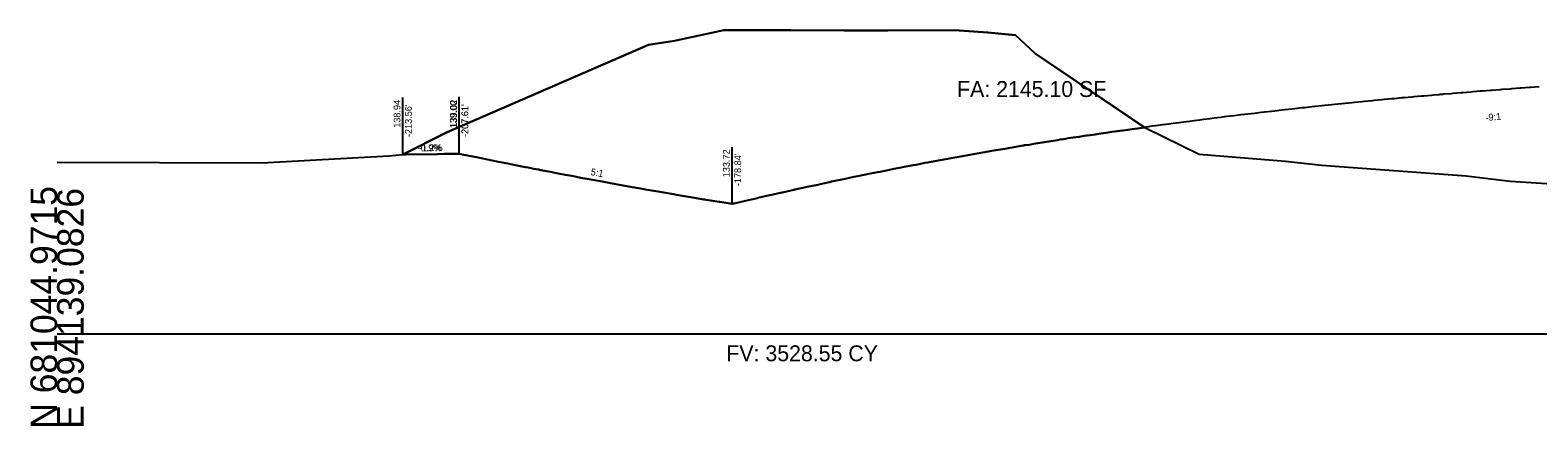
# Model space of a CAD drawing. Extents: x -26 to 4403, y -13 to 9578.
# Drawn here: x 1997.2 to 2156.1, y 490.3 to 532.1 of the extents above; entities that cross this region are included whole.
import ezdxf

# ---------------------------------------------------------------- set-up
doc = ezdxf.new("R2010")
doc.units = 0
for name, color, linetype in [('Draft_XS_Grid', 7, 'Continuous'), ('DRAINAGE_SPUR_DIKES', 7, 'Continuous'), ('DTM_CORRIDOR', 7, 'Continuous'), ('DTM_X_GROUND', 7, 'Continuous'), ('SLOPE_STAKES_FILL', 7, 'Continuous'), ('XS_CELL', 7, 'Continuous'), ('XS_M_SHAPES_EARTHWORK', 7, 'Continuous'), ('XS_P_GROUND', 7, 'Continuous'), ('XS_P_TX_CLEARZONE', 7, 'Continuous'), ('XS_P_TX_FS_BS', 7, 'Continuous'), ('XS_SHEET_EW_TX_AREA', 7, 'Continuous'), ('XS_SHEET_EW_TX_VOLUME', 7, 'Continuous')]:
    doc.layers.add(name, color=color, linetype=linetype)

msp = doc.modelspace()

# ---------------------------------------------------------------- linework, layer by layer
at = {"layer": 'DTM_X_GROUND'}
msp.add_lwpolyline([(2000, 518.14), (2021.58, 518.06), (2034.99, 518.8), (2035.72, 518.86), (2036.44, 518.94), (2041.12, 521.3), (2062.37, 530.51), (2065.11, 530.92), (2070.29, 532.04), (2077.35, 532.04), (2082.97, 532.02), (2087.59, 532.02), (2094.63, 532.05), (2098.14, 531.79), (2101.06, 531.53), (2103.12, 529.59), (2114.67, 521.78), (2120.42, 518.96), (2129.5, 518.23), (2133.32, 517.8), (2148.57, 516.67), (2153.19, 516.13), (2186.74, 513.99)], dxfattribs=at)
at = {"layer": 'XS_CELL'}
msp.add_line((2000, 500), (2250, 500), dxfattribs=at)
at = {"layer": 'XS_M_SHAPES_EARTHWORK'}
msp.add_lwpolyline([(2036.44, 518.94), (2041.12, 521.3), (2062.37, 530.51), (2065.11, 530.92), (2070.29, 532.04), (2077.35, 532.04), (2082.97, 532.02), (2087.59, 532.02), (2094.63, 532.05), (2098.14, 531.79), (2101.06, 531.53), (2103.12, 529.59), (2114.66, 521.79), (2114.43, 521.76), (2113.93, 521.69), (2113.34, 521.61), (2112.9, 521.55), (2112.37, 521.48), (2112.32, 521.47), (2112.33, 521.47), (2111.76, 521.39), (2111.2, 521.31), (2110.61, 521.23), (2110.06, 521.15), (2109.46, 521.06), (2108.91, 520.98), (2108.3, 520.89), (2107.77, 520.81), (2107.14, 520.72), (2106.62, 520.64), (2106.33, 520.59), (2106.1, 520.55), (2105.75, 520.5), (2105.47, 520.46), (2104.82, 520.35), (2104.32, 520.27), (2103.65, 520.17), (2103.17, 520.09), (2102.49, 519.97), (2102.01, 519.9), (2101.92, 519.88), (2101.86, 519.87), (2101.25, 519.77), (2100.86, 519.7), (2100.14, 519.58), (2099.7, 519.51), (2098.97, 519.38), (2098.54, 519.31), (2097.8, 519.18), (2097.39, 519.11), (2096.63, 518.97), (2096.23, 518.9), (2095.45, 518.76), (2095.07, 518.69), (2094.28, 518.55), (2093.91, 518.48), (2093.49, 518.41), (2093.31, 518.37), (2092.89, 518.3), (2092.72, 518.27), (2091.82, 518.1), (2091.49, 518.04), (2090.57, 517.86), (2090.25, 517.8), (2089.31, 517.62), (2089.01, 517.56), (2088.05, 517.37), (2087.76, 517.32), (2086.78, 517.12), (2086.51, 517.07), (2086.19, 517), (2086.11, 516.99), (2085.42, 516.85), (2085.26, 516.82), (2084.23, 516.6), (2084, 516.56), (2082.95, 516.34), (2082.74, 516.29), (2081.66, 516.07), (2081.48, 516.03), (2081.28, 515.98), (2081.24, 515.98), (2080.34, 515.78), (2080.21, 515.75), (2079.08, 515.51), (2078.94, 515.48), (2077.79, 515.23), (2077.67, 515.2), (2076.49, 514.94), (2076.4, 514.92), (2075.19, 514.65), (2075.12, 514.63), (2073.89, 514.35), (2073.84, 514.34), (2072.59, 514.06), (2072.57, 514.05), (2071.38, 513.77), (2071.37, 513.77), (2071.28, 513.75), (2071.16, 513.72), (2069.86, 513.93), (2069.8, 513.94), (2068.44, 514.16), (2068.31, 514.18), (2068.17, 514.2), (2066.81, 514.43), (2066.58, 514.47), (2065.29, 514.69), (2064.98, 514.74), (2063.75, 514.95), (2063.36, 515.02), (2062.21, 515.22), (2062.04, 515.25), (2061.67, 515.31), (2061.33, 515.37), (2060.64, 515.49), (2060.06, 515.6), (2059.07, 515.78), (2058.17, 515.94), (2057.48, 516.07), (2056.65, 516.22), (2055.88, 516.37), (2055.41, 516.45), (2054.91, 516.55), (2054.61, 516.6), (2054.27, 516.67), (2053.57, 516.8), (2052.64, 516.98), (2052.01, 517.1), (2051.01, 517.29), (2050.75, 517.34), (2050.28, 517.43), (2049.66, 517.56), (2049.36, 517.61), (2048.14, 517.86), (2047.71, 517.94), (2046.35, 518.21), (2046.05, 518.27), (2044.55, 518.58), (2044.38, 518.61), (2042.72, 518.95), (2042.7, 518.95), (2042.39, 519), (2042.38, 519), (2042.27, 519), (2042.06, 519), (2041.95, 519), (2041.72, 518.99), (2041.65, 518.99), (2041.46, 518.99), (2041.43, 518.99), (2041.34, 518.99), (2041.33, 518.99), (2040.84, 518.99), (2040.09, 518.98), (2036.77, 518.95)], close=True, dxfattribs=at)
msp.add_lwpolyline([(2156.26, 526.07), (2155.38, 526), (2155.23, 525.99), (2154.35, 525.93), (2154.21, 525.92), (2153.33, 525.85), (2153.18, 525.84), (2152.31, 525.78), (2152.15, 525.76), (2151.28, 525.7), (2151.12, 525.68), (2150.26, 525.62), (2150.08, 525.6), (2149.23, 525.53), (2149.05, 525.52), (2148.2, 525.45), (2148.02, 525.44), (2147.17, 525.37), (2146.98, 525.35), (2146.14, 525.28), (2146.09, 525.27), (2145.84, 525.25), (2145.71, 525.24), (2145.13, 525.19), (2144.92, 525.17), (2144.09, 525.1), (2143.87, 525.08), (2143.06, 525.01), (2142.83, 524.99), (2142.02, 524.92), (2141.78, 524.9), (2140.98, 524.82), (2140.74, 524.8), (2139.94, 524.73), (2139.69, 524.7), (2138.89, 524.63), (2138.64, 524.6), (2137.85, 524.53), (2137.58, 524.5), (2136.8, 524.42), (2136.53, 524.39), (2135.76, 524.32), (2135.47, 524.29), (2134.71, 524.21), (2134.42, 524.18), (2133.66, 524.1), (2133.36, 524.07), (2132.6, 523.99), (2132.3, 523.96), (2131.55, 523.87), (2131.23, 523.84), (2130.5, 523.76), (2130.17, 523.72), (2129.44, 523.64), (2129.1, 523.6), (2128.38, 523.52), (2128.03, 523.48), (2127.32, 523.4), (2126.96, 523.36), (2126.25, 523.27), (2125.89, 523.23), (2125.19, 523.15), (2124.81, 523.1), (2124.12, 523.02), (2123.73, 522.97), (2123.05, 522.89), (2122.65, 522.84), (2121.98, 522.76), (2121.57, 522.7), (2120.91, 522.62), (2120.49, 522.57), (2119.84, 522.48), (2119.4, 522.43), (2118.76, 522.34), (2118.31, 522.28), (2117.68, 522.2), (2117.22, 522.14), (2116.6, 522.06), (2116.13, 521.99), (2115.51, 521.91), (2115.03, 521.85), (2114.66, 521.79), (2114.67, 521.78), (2120.42, 518.96), (2129.5, 518.23), (2133.32, 517.8), (2148.57, 516.67), (2153.19, 516.13), (2186.74, 513.99)], dxfattribs=at)
at = {"layer": 'XS_P_GROUND'}
for points in [[(2114.66, 521.79), (2103.12, 529.59), (2101.06, 531.53), (2098.14, 531.79), (2094.63, 532.05), (2087.59, 532.02), (2082.97, 532.02), (2077.35, 532.04), (2070.29, 532.04), (2065.11, 530.92), (2062.37, 530.51), (2041.12, 521.3), (2036.44, 518.94)], [(2156.26, 526.07), (2155.38, 526), (2155.23, 525.99), (2154.35, 525.93), (2154.21, 525.92), (2153.33, 525.85), (2153.18, 525.84), (2152.31, 525.78), (2152.15, 525.76), (2151.28, 525.7), (2151.12, 525.68), (2150.26, 525.62), (2150.08, 525.6), (2149.23, 525.53), (2149.05, 525.52), (2148.2, 525.45), (2148.02, 525.44), (2147.17, 525.37), (2146.98, 525.35), (2146.14, 525.28), (2146.09, 525.27), (2145.84, 525.25), (2145.71, 525.24), (2145.13, 525.19), (2144.92, 525.17), (2144.09, 525.1), (2143.87, 525.08), (2143.06, 525.01), (2142.83, 524.99), (2142.02, 524.92), (2141.78, 524.9), (2140.98, 524.82), (2140.74, 524.8), (2139.94, 524.73), (2139.69, 524.7), (2138.89, 524.63), (2138.64, 524.6), (2137.85, 524.53), (2137.58, 524.5), (2136.8, 524.42), (2136.53, 524.39), (2135.76, 524.32), (2135.47, 524.29), (2134.71, 524.21), (2134.42, 524.18), (2133.66, 524.1), (2133.36, 524.07), (2132.6, 523.99), (2132.3, 523.96), (2131.55, 523.87), (2131.23, 523.84), (2130.5, 523.76), (2130.17, 523.72), (2129.44, 523.64), (2129.1, 523.6), (2128.38, 523.52), (2128.03, 523.48), (2127.32, 523.4), (2126.96, 523.36), (2126.25, 523.27), (2125.89, 523.23), (2125.19, 523.15), (2124.81, 523.1), (2124.12, 523.02), (2123.73, 522.97), (2123.05, 522.89), (2122.65, 522.84), (2121.98, 522.76), (2121.57, 522.7), (2120.91, 522.62), (2120.49, 522.57), (2119.84, 522.48), (2119.4, 522.43), (2118.76, 522.34), (2118.31, 522.28), (2117.68, 522.2), (2117.22, 522.14), (2116.6, 522.06), (2116.13, 521.99), (2115.51, 521.91), (2115.03, 521.85), (2114.43, 521.76), (2113.93, 521.69), (2113.34, 521.61), (2112.9, 521.55), (2112.37, 521.48), (2112.32, 521.47), (2112.33, 521.47), (2111.76, 521.39), (2111.2, 521.31), (2110.61, 521.23), (2110.06, 521.15), (2109.46, 521.06), (2108.91, 520.98), (2108.3, 520.89), (2107.77, 520.81), (2107.14, 520.72), (2106.62, 520.64), (2106.33, 520.59), (2106.1, 520.55), (2105.75, 520.5), (2105.47, 520.46), (2104.82, 520.35), (2104.32, 520.27), (2103.65, 520.17), (2103.17, 520.09), (2102.49, 519.97), (2102.01, 519.9), (2101.92, 519.88), (2101.86, 519.87), (2101.25, 519.77), (2100.86, 519.7), (2100.14, 519.58), (2099.7, 519.51), (2098.97, 519.38), (2098.54, 519.31), (2097.8, 519.18), (2097.39, 519.11), (2096.63, 518.97), (2096.23, 518.9), (2095.45, 518.76), (2095.07, 518.69), (2094.28, 518.55), (2093.91, 518.48), (2093.49, 518.41), (2093.31, 518.37), (2092.89, 518.3), (2092.72, 518.27), (2091.82, 518.1), (2091.49, 518.04), (2090.57, 517.86), (2090.25, 517.8), (2089.31, 517.62), (2089.01, 517.56), (2088.05, 517.37), (2087.76, 517.32), (2086.78, 517.12), (2086.51, 517.07), (2086.19, 517), (2086.11, 516.99), (2085.42, 516.85), (2085.26, 516.82), (2084.23, 516.6), (2084, 516.56), (2082.95, 516.34), (2082.74, 516.29), (2081.66, 516.07), (2081.48, 516.03), (2081.28, 515.98), (2081.24, 515.98), (2080.34, 515.78), (2080.21, 515.75), (2079.08, 515.51), (2078.94, 515.48), (2077.79, 515.23), (2077.67, 515.2), (2076.49, 514.94), (2076.4, 514.92), (2075.19, 514.65), (2075.12, 514.63), (2073.89, 514.35), (2073.84, 514.34), (2072.59, 514.06), (2072.57, 514.05), (2071.38, 513.77), (2071.37, 513.77), (2071.28, 513.75), (2071.28, 513.75), (2071.16, 513.72)], [(2086.19, 517), (2086.51, 517.07), (2086.78, 517.12), (2087.76, 517.32), (2088.05, 517.37), (2089.01, 517.56), (2089.31, 517.62), (2090.25, 517.8), (2090.57, 517.86), (2091.49, 518.04), (2091.82, 518.1), (2092.72, 518.27), (2092.89, 518.3), (2093.31, 518.37), (2093.49, 518.41), (2093.91, 518.48), (2094.28, 518.55), (2095.07, 518.69), (2095.45, 518.76), (2096.23, 518.9), (2096.63, 518.97), (2097.39, 519.11), (2097.8, 519.18), (2098.54, 519.31), (2098.97, 519.38), (2099.7, 519.51), (2100.14, 519.58), (2100.86, 519.7), (2101.25, 519.77), (2101.86, 519.87), (2101.92, 519.88), (2102.01, 519.9), (2102.49, 519.97), (2103.17, 520.09), (2103.65, 520.17), (2104.32, 520.27), (2104.82, 520.35), (2105.47, 520.46), (2105.75, 520.5), (2106.1, 520.55), (2106.33, 520.59), (2106.62, 520.64), (2107.14, 520.72), (2107.77, 520.81), (2108.3, 520.89), (2108.91, 520.98), (2109.46, 521.06), (2110.06, 521.15), (2110.61, 521.23), (2111.2, 521.31), (2111.76, 521.39), (2112.32, 521.47), (2112.33, 521.47)], [(2112.33, 521.47), (2112.37, 521.48), (2112.9, 521.55), (2113.34, 521.61), (2113.93, 521.69), (2114.43, 521.76), (2114.66, 521.79)], [(2112.33, 521.47), (2112.33, 521.47)], [(2042.06, 519), (2041.95, 519), (2041.72, 518.99), (2041.65, 518.99), (2041.46, 518.99), (2041.43, 518.99), (2041.34, 518.99), (2041.33, 518.99), (2040.84, 518.99), (2040.09, 518.98), (2036.77, 518.95), (2036.44, 518.94)], [(2036.44, 518.94), (2036.77, 518.95), (2040.09, 518.98), (2040.84, 518.99), (2041.33, 518.99), (2041.34, 518.99), (2041.43, 518.99), (2041.46, 518.99), (2041.65, 518.99), (2041.72, 518.99), (2041.95, 519), (2042.06, 519)], [(2042.39, 519), (2042.38, 519), (2042.27, 519), (2042.06, 519)], [(2042.06, 519), (2042.27, 519), (2042.39, 519)], [(2042.39, 519), (2042.7, 518.95), (2042.72, 518.95), (2044.38, 518.61), (2044.55, 518.58), (2046.05, 518.27), (2046.35, 518.21), (2047.71, 517.94), (2048.14, 517.86), (2049.36, 517.61), (2049.66, 517.56), (2050.28, 517.43), (2050.75, 517.34), (2051.01, 517.29), (2052.01, 517.1), (2052.64, 516.98), (2053.57, 516.8), (2054.27, 516.67), (2054.61, 516.6), (2054.91, 516.55), (2055.41, 516.45), (2055.88, 516.37), (2056.65, 516.22), (2057.48, 516.07), (2058.17, 515.94), (2059.07, 515.78), (2060.06, 515.6), (2060.64, 515.49), (2061.33, 515.37), (2061.67, 515.31), (2062.04, 515.25), (2062.21, 515.22), (2063.36, 515.02), (2063.75, 514.95), (2064.98, 514.74), (2065.29, 514.69), (2066.58, 514.47), (2066.81, 514.43), (2068.17, 514.2), (2068.31, 514.18), (2068.44, 514.16), (2069.8, 513.94), (2069.86, 513.93), (2071.16, 513.72)], [(2042.39, 519), (2042.7, 518.95), (2042.72, 518.95), (2044.38, 518.61), (2044.55, 518.58), (2046.05, 518.27), (2046.35, 518.21), (2047.71, 517.94), (2048.14, 517.86), (2049.36, 517.61), (2049.66, 517.56), (2050.28, 517.43), (2050.75, 517.34), (2051.01, 517.29), (2052.01, 517.1), (2052.64, 516.98), (2053.57, 516.8), (2054.27, 516.67), (2054.61, 516.6), (2054.91, 516.55), (2055.41, 516.45), (2055.88, 516.37), (2056.65, 516.22), (2057.48, 516.07), (2058.17, 515.94), (2059.07, 515.78), (2060.06, 515.6), (2060.64, 515.49), (2061.33, 515.37), (2061.67, 515.31), (2062.04, 515.25), (2062.21, 515.22), (2063.36, 515.02), (2063.75, 514.95), (2064.98, 514.74), (2065.29, 514.69), (2066.58, 514.47), (2066.81, 514.43), (2068.17, 514.2), (2068.31, 514.18), (2068.44, 514.16), (2069.8, 513.94), (2069.86, 513.93), (2071.16, 513.72)], [(2071.16, 513.72), (2071.28, 513.75), (2071.38, 513.77), (2072.57, 514.05), (2072.59, 514.06), (2073.84, 514.34), (2073.89, 514.35), (2075.12, 514.63), (2075.19, 514.65), (2076.4, 514.92), (2076.49, 514.94), (2077.67, 515.2), (2077.79, 515.23), (2078.94, 515.48), (2079.08, 515.51), (2080.21, 515.75), (2080.34, 515.78), (2081.24, 515.98), (2081.28, 515.98), (2081.48, 516.03), (2081.66, 516.07), (2082.74, 516.29), (2082.95, 516.34), (2084, 516.56), (2084.23, 516.6), (2085.26, 516.82), (2085.42, 516.85), (2086.11, 516.99), (2086.19, 517)]]:
    msp.add_lwpolyline(points, dxfattribs=at)
at = {"layer": 'XS_P_TX_CLEARZONE'}
for p, q in [((2036.44, 518.94), (2036.44, 524.94)), ((2036.44, 518.94), (2036.44, 524.94)), ((2036.44, 518.94), (2036.44, 524.94)), ((2036.44, 518.94), (2036.44, 524.94)), ((2036.44, 518.94), (2036.44, 524.94)), ((2036.44, 518.94), (2036.44, 524.94)), ((2036.44, 518.94), (2036.44, 524.94)), ((2036.44, 518.94), (2036.44, 524.94)), ((2036.44, 518.94), (2036.44, 524.94)), ((2042.39, 519.02), (2042.39, 525.02)), ((2042.39, 519), (2042.39, 525)), ((2042.39, 519), (2042.39, 525)), ((2071.16, 513.72), (2071.16, 519.72)), ((2071.16, 513.72), (2071.16, 519.72)), ((2071.16, 513.72), (2071.16, 519.72)), ((2071.16, 513.72), (2071.16, 519.72)), ((2071.16, 513.72), (2071.16, 519.72)), ((2071.16, 513.72), (2071.16, 519.72))]:
    msp.add_line(p, q, dxfattribs=at)

# ---------------------------------------------------------------- texts
at = {"layer": 'Draft_XS_Grid'}
msp.add_text('-', height=0.0001, dxfattribs=at).set_placement((2000, 500))
at = {"layer": 'DRAINAGE_SPUR_DIKES'}
msp.add_text('X', height=0.12, dxfattribs=at).set_placement((2042.35, 518.94))
at = {"layer": 'DTM_CORRIDOR'}
for p in [(2036.4, 518.88), (2071.12, 513.66)]:
    msp.add_text('X', height=0.12, dxfattribs=at).set_placement(p)
at = {"layer": 'SLOPE_STAKES_FILL'}
msp.add_text('X', height=0.12, dxfattribs=at).set_placement((2036.4, 518.88))
at = {"layer": 'XS_CELL'}
for s, p in [('N 681044.9715', (2000, 490)), ('E 894139.0826', (2002.8, 490))]:
    msp.add_text(s, height=2.8, rotation=90, dxfattribs=at).set_placement(p)
at = {"layer": 'XS_P_TX_CLEARZONE'}
for s, p in [('138.94', (2036.2, 521.75)), ('138.94', (2036.2, 521.75)), ('138.94', (2036.2, 521.75)), ('138.94', (2036.2, 521.75)), ('138.94', (2036.2, 521.75)), ('138.94', (2036.2, 521.75)), ('138.94', (2036.2, 521.75)), ('138.94', (2036.2, 521.75)), ('138.94', (2036.2, 521.75)), ('139.02', (2042.15, 521.76)), ('139.00', (2042.15, 521.69)), ('139.00', (2042.15, 521.69)), ("-213.56'", (2037.4, 520.77)), ("-213.56'", (2037.4, 520.77)), ("-213.56'", (2037.4, 520.77)), ("-213.56'", (2037.4, 520.77)), ("-213.56'", (2037.4, 520.77)), ("-213.56'", (2037.4, 520.77)), ("-213.56'", (2037.4, 520.77)), ("-213.56'", (2037.4, 520.77)), ("-213.56'", (2037.4, 520.77)), ("-207.61'", (2043.35, 520.79)), ("-207.61'", (2043.35, 520.77)), ("-207.61'", (2043.35, 520.77)), ('133.72', (2070.92, 516.53)), ('133.72', (2070.92, 516.53)), ('133.72', (2070.92, 516.53)), ('133.72', (2070.92, 516.53)), ('133.72', (2070.92, 516.53)), ('133.72', (2070.92, 516.53)), ("-178.84'", (2072.12, 515.59)), ("-178.84'", (2072.12, 515.59)), ("-178.84'", (2072.12, 515.59)), ("-178.84'", (2072.12, 515.59)), ("-178.84'", (2072.12, 515.59)), ("-178.84'", (2072.12, 515.59))]:
    msp.add_text(s, height=0.72, rotation=90, dxfattribs=at).set_placement(p)
at = {"layer": 'XS_P_TX_FS_BS'}
for s, rotation, p in [('-9:1', 6.048, (2150.64, 522.45)), ('-9:1', 6.048, (2150.64, 522.45)), ('-9:1', 6.048, (2150.64, 522.45)), ('-0.9%', 0.5394, (2038.02, 519.26)), ('-0.9%', 0.5394, (2038.02, 519.26)), ('-1.2%', 0.6977, (2038.13, 519.27)), ('5:1', 349.5733, (2056.22, 516.78)), ('5:1', 349.605, (2056.22, 516.77)), ('5:1', 349.605, (2056.22, 516.77))]:
    msp.add_text(s, height=0.72, rotation=rotation, dxfattribs=at).set_placement(p)
at = {"layer": 'XS_SHEET_EW_TX_AREA'}
msp.add_text('FA: 2145.10 SF', height=1.68, dxfattribs=at).set_placement((2094.89, 525))
at = {"layer": 'XS_SHEET_EW_TX_VOLUME'}
msp.add_text('FV: 3528.55 CY', height=1.68, dxfattribs=at).set_placement((2070.56, 497.12))

doc.saveas('drawing.dxf')
